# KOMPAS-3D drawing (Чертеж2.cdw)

Referenced files: Чертеж2.cdw
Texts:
  Екстрактор колонний
  Виталий
  Samsung Electronics
  Текст на чертеже
  Размерные надписи
  Шероховатость
  Линия-выноска #1
  Линия-выноска #2
  Линия-выноска #3
  Отклонения формы и база
  Заголовок таблицы
  Ячейка таблицы
  Стрелка вида
  Обозначение изменения
  Фигурная скобка
  Номер узла
  Марка координационной оси
  Выносная надпись
  Обозначение узла
  Марка/позиционное обозначение с линией-выноской
  Марка/позиционное обозначение на линии
  Марка/позиционное обозначение без линии-выноски
  Технічна характеристика.
  Найменування
  Поз.
  Кіл.
  Вхід сокостружної суміші.
  Вихід соку на виробництво.
  Вхід жомопресової води.
  Вхід аміачної води.
  Вхід формаліна.
  Вихід жому.
  Злив аварійний.
  Лаз.
  Вікно смотрове
  Кран пробний.
  Приєднання термометра.
  Приєднання рН-метра
  Приєднання вказаного рівня
  Позначення
  ГОСТ
  Довжина
  шва,мм
  Маса наплавлен-
  ного металу,кг
  Призначення патрубків
  Таблиця 1
  Таблиця 2
  Апарат призначений для обезцукрення бурякової стружки за
  допомогою омиванням дифузійним соком.
  Продуктивність апарата 3000 т\добу.
  Площа сита:-загальна-живий перетин 21.9-37м 2 .
  Втрати цукру в жомі при відсутності пресування жому 0.47%
  Встановлена потужність 92 кВт.
  Коефіцієнт автоматизації 1.0.
  Втрати цукру в пресованому жомі при віджимі до 18-20% СВ і
  поверненні жомопресової води 0.27% до маси буряка.
  Величина відкачки дифузійного соку 120% до маси буряка.
  Діаметр апарата внутрішній 600мм.
  Діаметр трубовалу  зовнішній 2600мм.
  Висота активна дифундування 12000мм
  Привід тубовалу мотор-редуктор(2шт.),електро двигун(2шт)
  МР3-800-13-5Ф-1В4ПФМ-225,МГУХЛ4N=37кВт п=1060 про.\хв
  Відкрита зубчаста передача 8.5
  Частота обертання трубовалу мін-0.2об.\хв., макс.-0.7 об.\хв.
  Пристрій для вивантаження жому-тип
  привід:-редуктор-електродвигун: шнек-2шт. Ц2У-200-31.5-21
  4А1325УЗ N=7.5 кВт п=1460 про.\хв.
  Екстрактор
  колонний
  Янковий М.Г.
Dimensions and other numbers on the sheet: 03-3604.ДП.001.ЗВ; 7; 3420; 20437; 16182; 13737; 11337; 8937; 6537; 3750; 2715; 3210; 2425; 8968; 7250; 6250; 7196; 6574; 16387; 14137; 77; 12137; 11737; 9337; 4137; 4537; 6937; 1600; 5; 19; 1; 10; 3; 11; 4 отв.; 9 отв.; 25; 2; 6; 4; 250; 300; 80; 150; 0,25; 0.25; 1.0; 0.6; 14; 16; 5264-80; 0.16; 6.2; 10.4; 0.96; 11.60; 0.17; 5.50; 2.40; 0.84; 98.02; 03-3604.ДП.001.ЗВ-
